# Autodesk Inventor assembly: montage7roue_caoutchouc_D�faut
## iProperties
Created: 2011-01
Part Number: montage7roue_caoutchouc_D�faut
Document SubType Name: Assembly
Designer: eric
Mass: 3043.31 g
Surface Area: 5165.36 cm^2
Volume: 3043.31 cm^3
Density: 1 g/cm^3
Author: eric
